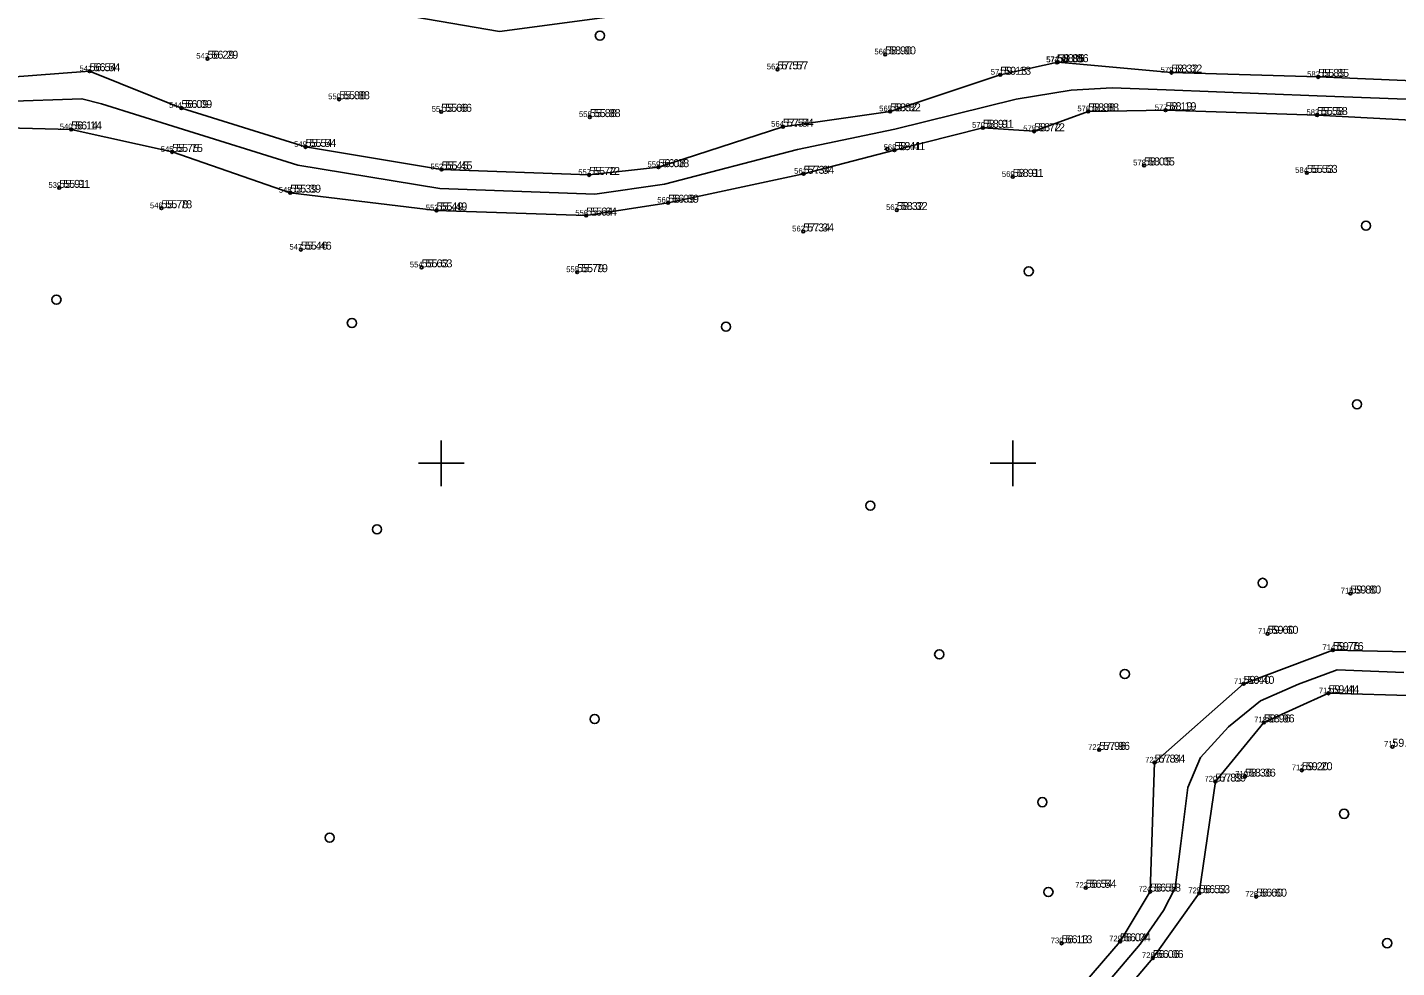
# Model space of a CAD drawing. Extents: x 554846 to 556995, y 6445875 to 6446723.
# Drawn here: x 555263.8 to 555383.6, y 6446205.9 to 6446288.1 of the extents above; entities that cross this region are included whole.
import ezdxf

# ---------------------------------------------------------------- set-up
doc = ezdxf.new("R2010")
doc.units = 0
for name, color, linetype in [('HALJASTUS', 7, 'Continuous'), ('KORGUS-EH2000', 7, 'Continuous'), ('MOOTKORG-EH2000', 7, 'Continuous'), ('MOOTMPUNKT', 7, 'Continuous'), ('MOOTNR', 7, 'Continuous'), ('MOOTPIIR', 7, 'Continuous'), ('TEE', 7, 'Continuous'), ('VORK', 7, 'Continuous')]:
    doc.layers.add(name, color=color, linetype=linetype)

msp = doc.modelspace()

# ---------------------------------------------------------------- linework, layer by layer
at = {"layer": 'HALJASTUS'}
for centre in [(555313.87, 6446287.39), (555380.87, 6446270.77), (555351.38, 6446266.79), (555266.34, 6446264.31), (555292.18, 6446262.26), (555324.9, 6446261.94), (555380.09, 6446255.16), (555337.52, 6446246.3), (555294.38, 6446244.22), (555371.83, 6446239.54), (555343.55, 6446233.29), (555359.78, 6446231.57), (555313.41, 6446227.64), (555352.56, 6446220.37), (555378.96, 6446219.35), (555290.24, 6446217.27), (555353.1, 6446212.51), (555382.73, 6446208.04)]:
    msp.add_circle(centre, 0.4, dxfattribs=at)
at = {"layer": 'KORGUS-EH2000'}
for centre in [(555338.82, 6446285.75), (555279.55, 6446285.37), (555329.4, 6446284.44), (555353.92, 6446285.07), (555269.24, 6446284.28), (555348.89, 6446283.97), (555363.86, 6446284.16), (555376.7, 6446283.78), (555277.27, 6446281.06), (555291.06, 6446281.83), (555363.35, 6446280.87), (555299.99, 6446280.73), (555312.99, 6446280.27), (555339.25, 6446280.77), (555356.58, 6446280.77), (555376.59, 6446280.45), (555267.63, 6446279.19), (555329.88, 6446279.43), (555347.37, 6446279.33), (555351.85, 6446279.03), (555288.13, 6446277.66), (555339.63, 6446277.38), (555276.46, 6446277.22), (555361.46, 6446276.04), (555300.03, 6446275.69), (555312.93, 6446275.21), (555318.99, 6446275.89), (555331.69, 6446275.31), (555349.98, 6446275.04), (555375.7, 6446275.39), (555266.59, 6446274.08), (555286.79, 6446273.66), (555319.84, 6446272.78), (555275.52, 6446272.3), (555299.58, 6446272.11), (555312.67, 6446271.66), (555339.84, 6446272.14), (555331.66, 6446270.27), (555287.72, 6446268.68), (555298.28, 6446267.13), (555311.88, 6446266.71), (555379.51, 6446238.61), (555372.27, 6446235.09), (555377.98, 6446233.66), (555370.17, 6446230.71), (555377.59, 6446229.89), (555371.94, 6446227.34), (555357.54, 6446224.94), (555383.18, 6446225.21), (555362.39, 6446223.83), (555367.7, 6446222.17), (555370.29, 6446222.6), (555375.26, 6446223.16), (555356.36, 6446212.88), (555362, 6446212.55), (555366.29, 6446212.41), (555371.27, 6446212.11), (555354.25, 6446208.03), (555359.36, 6446208.2), (555362.23, 6446206.74)]:
    msp.add_circle(centre, 0.125, dxfattribs=at)
at = {"layer": 'MOOTMPUNKT'}
for centre in [(555338.82, 6446285.75), (555279.55, 6446285.37), (555329.4, 6446284.44), (555353.84, 6446285.05), (555353.92, 6446285.07), (555269.24, 6446284.28), (555348.89, 6446283.97), (555363.86, 6446284.16), (555376.7, 6446283.78), (555277.27, 6446281.06), (555291.06, 6446281.83), (555363.35, 6446280.87), (555299.99, 6446280.73), (555312.99, 6446280.27), (555339.25, 6446280.77), (555356.58, 6446280.77), (555376.59, 6446280.45), (555267.63, 6446279.19), (555329.88, 6446279.43), (555347.37, 6446279.33), (555351.85, 6446279.03), (555288.13, 6446277.66), (555339.01, 6446277.48), (555339.63, 6446277.38), (555276.46, 6446277.22), (555361.46, 6446276.04), (555300.03, 6446275.69), (555312.93, 6446275.21), (555318.99, 6446275.89), (555331.69, 6446275.31), (555349.98, 6446275.04), (555375.7, 6446275.39), (555266.59, 6446274.08), (555286.79, 6446273.66), (555319.84, 6446272.78), (555275.52, 6446272.3), (555299.58, 6446272.11), (555312.67, 6446271.66), (555339.84, 6446272.14), (555331.66, 6446270.27), (555287.72, 6446268.68), (555298.28, 6446267.13), (555311.88, 6446266.71), (555379.51, 6446238.61), (555372.27, 6446235.09), (555377.98, 6446233.66), (555370.17, 6446230.71), (555377.59, 6446229.89), (555371.94, 6446227.34), (555357.54, 6446224.94), (555383.18, 6446225.21), (555362.39, 6446223.83), (555367.7, 6446222.17), (555370.29, 6446222.6), (555375.26, 6446223.16), (555356.36, 6446212.88), (555362, 6446212.55), (555366.29, 6446212.41), (555371.27, 6446212.11), (555354.25, 6446208.03), (555359.36, 6446208.2), (555362.23, 6446206.74)]:
    msp.add_circle(centre, 0.125, dxfattribs=at)
at = {"layer": 'MOOTPIIR'}
msp.add_lwpolyline([(555188.08, 6446295.67), (555274.45, 6446293.03), (555305.1, 6446287.75), (555351.91, 6446294.02), (555415.21, 6446294.68), (555454.1, 6446280.49), (555476.52, 6446236.63), (555494.98, 6446232.67), (555576.07, 6446239.92), (555660.79, 6446267.96), (555725.41, 6446281.48), (555817.05, 6446350.75)], dxfattribs=at)
at = {"layer": 'TEE'}
for points in [[(555385.66, 6446283.42), (555376.7, 6446283.78), (555363.86, 6446284.16), (555353.92, 6446285.07), (555348.89, 6446283.97), (555339.25, 6446280.77), (555329.88, 6446279.43), (555318.99, 6446275.89), (555312.93, 6446275.21), (555300.03, 6446275.69), (555288.13, 6446277.66), (555277.27, 6446281.06), (555269.24, 6446284.28), (555254.63, 6446283.19)], [(555254.94, 6446281.41), (555268.57, 6446281.88), (555270.28, 6446281.42), (555277, 6446279.33), (555287.46, 6446276.08), (555299.87, 6446274.02), (555313.44, 6446273.54), (555319.51, 6446274.41), (555331.16, 6446277.44), (555339.66, 6446279.22), (555350.29, 6446281.85), (555355.08, 6446282.63), (555358.66, 6446282.84), (555363.41, 6446282.66), (555376.59, 6446282.14), (555385.92, 6446281.77)], [(555385.91, 6446279.94), (555376.59, 6446280.45), (555363.35, 6446280.87), (555356.58, 6446280.77), (555351.85, 6446279.03), (555347.37, 6446279.33), (555339.63, 6446277.38), (555331.69, 6446275.31), (555319.84, 6446272.78), (555312.67, 6446271.66), (555299.58, 6446272.11), (555286.79, 6446273.66), (555276.46, 6446277.22), (555267.63, 6446279.19), (555255.15, 6446279.51)], [(555247.52, 6446162.12), (555265.47, 6446160.79), (555276.34, 6446159.56), (555286.43, 6446157.68), (555298.36, 6446153.15), (555308.59, 6446150.29), (555319.62, 6446148.54), (555327.84, 6446149.13), (555331.85, 6446150.36), (555334.58, 6446153.35), (555334.79, 6446162.55), (555336.04, 6446172.56), (555338.65, 6446179.44), (555343.2, 6446186.87), (555348.65, 6446195.75), (555359.36, 6446208.2), (555362, 6446212.55), (555362.39, 6446223.83), (555370.17, 6446230.71), (555377.98, 6446233.66), (555385.78, 6446233.47)], [(555384.18, 6446231.72), (555378.36, 6446231.93), (555374.96, 6446230.7), (555371.65, 6446229.24), (555368.84, 6446226.96), (555366.41, 6446224.28), (555365.3, 6446221.65), (555364.68, 6446216.75), (555364.19, 6446212.88), (555363.17, 6446210.91), (555361.12, 6446207.96), (555350.96, 6446195.96)], [(555385.54, 6446229.68), (555377.59, 6446229.89), (555371.94, 6446227.34), (555367.7, 6446222.17), (555366.29, 6446212.41), (555362.23, 6446206.74), (555351.69, 6446194.25), (555346.07, 6446185.37), (555342.02, 6446178.62), (555340, 6446174.09), (555338.06, 6446163.9), (555338.78, 6446155.44), (555337.33, 6446148.82), (555334.66, 6446147.05), (555328.59, 6446146.01), (555319.3, 6446144.84), (555307.94, 6446146.59), (555297.14, 6446150.18), (555285.78, 6446154.2), (555276.24, 6446155.86), (555265.44, 6446157.09), (555246.52, 6446158.61)]]:
    msp.add_lwpolyline(points, dxfattribs=at)
at = {"layer": 'VORK'}
for p, q in [((555300, 6446252), (555300, 6446248)), ((555350, 6446252), (555350, 6446248)), ((555298, 6446250), (555302, 6446250)), ((555348, 6446250), (555352, 6446250))]:
    msp.add_line(p, q, dxfattribs=at)

# ---------------------------------------------------------------- texts
at = {"layer": 'KORGUS-EH2000'}
for s, p in [('56.29', (555279.9, 6446285.37)), ('58.90', (555339.17, 6446285.75)), ('58.86', (555354.27, 6446285.07)), ('56.54', (555269.59, 6446284.28)), ('57.57', (555329.75, 6446284.44)), ('59.13', (555349.24, 6446283.97)), ('58.32', (555364.21, 6446284.16)), ('55.85', (555377.05, 6446283.78)), ('55.88', (555291.41, 6446281.83)), ('56.09', (555277.62, 6446281.06)), ('55.66', (555300.34, 6446280.73)), ('55.88', (555313.34, 6446280.27)), ('58.82', (555339.6, 6446280.77)), ('58.88', (555356.93, 6446280.77)), ('58.19', (555363.7, 6446280.87)), ('55.58', (555376.94, 6446280.45)), ('56.14', (555267.98, 6446279.19)), ('57.54', (555330.23, 6446279.43)), ('58.91', (555347.72, 6446279.33)), ('58.72', (555352.2, 6446279.03)), ('55.75', (555276.81, 6446277.22)), ('55.54', (555288.48, 6446277.66)), ('58.41', (555339.98, 6446277.38)), ('55.45', (555300.38, 6446275.69)), ('56.08', (555319.34, 6446275.89)), ('58.05', (555361.81, 6446276.04)), ('55.72', (555313.28, 6446275.21)), ('57.34', (555332.04, 6446275.31)), ('58.91', (555350.33, 6446275.04)), ('55.53', (555376.05, 6446275.39)), ('55.91', (555266.94, 6446274.08)), ('55.39', (555287.14, 6446273.66)), ('55.78', (555275.87, 6446272.3)), ('55.49', (555299.93, 6446272.11)), ('56.09', (555320.19, 6446272.78)), ('58.32', (555340.19, 6446272.14)), ('55.64', (555313.02, 6446271.66)), ('57.34', (555332.01, 6446270.27)), ('55.46', (555288.07, 6446268.68)), ('55.63', (555298.63, 6446267.13)), ('55.79', (555312.23, 6446266.71)), ('59.80', (555379.86, 6446238.61)), ('59.60', (555372.62, 6446235.09)), ('59.76', (555378.33, 6446233.66)), ('59.40', (555370.52, 6446230.71)), ('59.44', (555377.94, 6446229.89)), ('58.96', (555372.29, 6446227.34)), ('57.96', (555357.89, 6446224.94)), ('57.84', (555362.73, 6446223.83)), ('59.20', (555375.61, 6446223.16)), ('57.89', (555368.05, 6446222.17)), ('58.36', (555370.64, 6446222.6)), ('56.54', (555356.71, 6446212.88)), ('56.58', (555362.35, 6446212.55)), ('56.53', (555366.64, 6446212.41)), ('56.60', (555371.62, 6446212.11)), ('56.13', (555354.6, 6446208.03)), ('56.04', (555359.71, 6446208.2)), ('56.06', (555362.58, 6446206.74))]:
    msp.add_text(s, height=0.7, dxfattribs=at).set_placement(p)
at = {"layer": 'MOOTKORG-EH2000'}
for s, p in [('56.29', (555279.55, 6446285.37)), ('58.90', (555338.82, 6446285.75)), ('58.85', (555353.84, 6446285.05)), ('58.86', (555353.92, 6446285.07)), ('56.54', (555269.24, 6446284.28)), ('57.57', (555329.4, 6446284.44)), ('59.13', (555348.89, 6446283.97)), ('58.32', (555363.86, 6446284.16)), ('55.85', (555376.7, 6446283.78)), ('55.88', (555291.06, 6446281.83)), ('56.09', (555277.27, 6446281.06)), ('55.66', (555299.99, 6446280.73)), ('55.88', (555312.99, 6446280.27)), ('58.82', (555339.25, 6446280.77)), ('58.88', (555356.58, 6446280.77)), ('58.19', (555363.35, 6446280.87)), ('55.58', (555376.59, 6446280.45)), ('56.14', (555267.63, 6446279.19)), ('57.54', (555329.88, 6446279.43)), ('58.91', (555347.37, 6446279.33)), ('58.72', (555351.85, 6446279.03)), ('55.75', (555276.46, 6446277.22)), ('55.54', (555288.13, 6446277.66)), ('58.41', (555339.63, 6446277.38)), ('55.45', (555300.03, 6446275.69)), ('56.08', (555318.99, 6446275.89)), ('58.05', (555361.46, 6446276.04)), ('55.72', (555312.93, 6446275.21)), ('57.34', (555331.69, 6446275.31)), ('58.91', (555349.98, 6446275.04)), ('55.53', (555375.7, 6446275.39)), ('55.91', (555266.59, 6446274.08)), ('55.39', (555286.79, 6446273.66)), ('55.78', (555275.52, 6446272.3)), ('55.49', (555299.58, 6446272.11)), ('56.09', (555319.84, 6446272.78)), ('58.32', (555339.84, 6446272.14)), ('55.64', (555312.67, 6446271.66)), ('57.34', (555331.66, 6446270.27)), ('55.46', (555287.72, 6446268.68)), ('55.63', (555298.28, 6446267.13)), ('55.79', (555311.88, 6446266.71)), ('59.80', (555379.51, 6446238.61)), ('59.60', (555372.27, 6446235.09)), ('59.76', (555377.98, 6446233.66)), ('59.40', (555370.17, 6446230.71)), ('59.44', (555377.59, 6446229.89)), ('58.96', (555371.94, 6446227.34)), ('59.25', (555383.18, 6446225.21)), ('57.96', (555357.54, 6446224.94)), ('57.84', (555362.39, 6446223.83)), ('59.20', (555375.26, 6446223.16)), ('57.89', (555367.7, 6446222.17)), ('58.36', (555370.29, 6446222.6)), ('56.54', (555356.36, 6446212.88)), ('56.58', (555362, 6446212.55)), ('56.53', (555366.29, 6446212.41)), ('56.60', (555371.27, 6446212.11)), ('56.13', (555354.25, 6446208.03)), ('56.04', (555359.36, 6446208.2)), ('56.06', (555362.23, 6446206.74))]:
    msp.add_text(s, height=0.7, dxfattribs=at).set_placement(p)
at = {"layer": 'MOOTNR'}
for s, p in [('543', (555278.57, 6446285.37)), ('566', (555337.88, 6446285.75)), ('541', (555268.36, 6446284.28)), ('563', (555328.47, 6446284.44)), ('574', (555352.89, 6446285.07)), ('573', (555352.92, 6446285.05)), ('579', (555362.91, 6446284.16)), ('571', (555348.06, 6446283.97)), ('582', (555375.73, 6446283.78)), ('550', (555290.11, 6446281.83)), ('544', (555276.19, 6446281.06)), ('551', (555299.16, 6446280.73)), ('565', (555338.3, 6446280.77)), ('576', (555355.63, 6446280.77)), ('577', (555362.4, 6446280.87)), ('583', (555375.67, 6446280.45)), ('558', (555312.04, 6446280.27)), ('564', (555328.85, 6446279.43)), ('570', (555346.42, 6446279.33)), ('540', (555266.63, 6446279.19)), ('575', (555350.9, 6446279.03)), ('545', (555275.46, 6446277.22)), ('549', (555287.13, 6446277.66)), ('568', (555338.68, 6446277.38)), ('552', (555299.05, 6446275.69)), ('559', (555318.04, 6446275.89)), ('578', (555360.51, 6446276.04)), ('557', (555311.98, 6446275.21)), ('561', (555330.86, 6446275.31)), ('569', (555349.03, 6446275.04)), ('584', (555374.68, 6446275.39)), ('539', (555265.64, 6446274.08)), ('548', (555285.79, 6446273.66)), ('546', (555274.52, 6446272.3)), ('553', (555298.65, 6446272.11)), ('560', (555318.89, 6446272.78)), ('567', (555338.9, 6446272.14)), ('556', (555311.72, 6446271.66)), ('562', (555330.69, 6446270.27)), ('547', (555286.72, 6446268.68)), ('554', (555297.25, 6446267.13)), ('555', (555310.93, 6446266.71)), ('715', (555378.66, 6446238.61)), ('716', (555371.42, 6446235.09)), ('714', (555377.06, 6446233.66)), ('717', (555369.32, 6446230.71)), ('713', (555376.76, 6446229.89)), ('718', (555371.09, 6446227.34)), ('722', (555356.57, 6446224.94)), ('711', (555382.45, 6446225.21)), ('721', (555361.56, 6446223.83)), ('712', (555374.38, 6446223.16)), ('720', (555366.75, 6446222.17)), ('719', (555369.44, 6446222.6)), ('723', (555355.44, 6446212.88)), ('724', (555360.98, 6446212.55)), ('725', (555365.34, 6446212.41)), ('726', (555370.32, 6446212.11)), ('730', (555353.3, 6446208.03)), ('729', (555358.41, 6446208.2)), ('728', (555361.28, 6446206.74))]:
    msp.add_text(s, height=0.5, dxfattribs=at).set_placement(p)

doc.saveas('drawing.dxf')
